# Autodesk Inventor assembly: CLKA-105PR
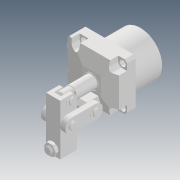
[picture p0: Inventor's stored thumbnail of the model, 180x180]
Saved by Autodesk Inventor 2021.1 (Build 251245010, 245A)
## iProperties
Created: 2018-07
Part Number: CLKA-105PR
Description: STEP AP203
Document SubType Name: Assembly
Designer: user
Title: CLKA-105P-R.STEP
Revision Number: ÈÎºÎ
Sending System: SolidWorks 2015
Preprocessor: SwSTEP 2.0
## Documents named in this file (11)
- D:\Vault_2016\Projekty\Clamptek\Hydraulic\CLKA-P\Inventor\CLKA-105PR\CLKA-105PR.iam
- D:\Vault_2016\Projekty\Clamptek\Hydraulic\CLKA-P\Inventor\CLKA-105PR\CLKA-105P-R-benti.ipt
- D:\Vault_2016\Projekty\Clamptek\Hydraulic\CLKA-P\Inventor\CLKA-105PR\duanxiao105.ipt
- D:\Vault_2016\Projekty\Clamptek\Hydraulic\CLKA-P\Inventor\CLKA-105PR\kahuang01.ipt
- D:\Vault_2016\Projekty\Clamptek\Hydraulic\CLKA-P\Inventor\CLKA-105PR\kahuang02.ipt
- D:\Vault_2016\Projekty\Clamptek\Hydraulic\CLKA-P\Inventor\CLKA-105PR\liangan105.ipt
- D:\Vault_2016\Projekty\Clamptek\Hydraulic\CLKA-P\Inventor\CLKA-105PR\luomu105.ipt
- D:\Vault_2016\Projekty\Clamptek\Hydraulic\CLKA-P\Inventor\CLKA-105PR\luosi105.ipt
- D:\Vault_2016\Projekty\Clamptek\Hydraulic\CLKA-P\Inventor\CLKA-105PR\yabi105.ipt
- D:\Vault_2016\Projekty\Clamptek\Hydraulic\CLKA-P\Inventor\CLKA-105PR\zhangxiao105.ipt
- D:\Vault_2016\Projekty\Clamptek\Hydraulic\CLKA-P\Inventor\CLKA-105PR\¶ÂÍ·G8-3.ipt
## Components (17 placed, 17 different names)
1. CLKA-105P-R-benti_1
2. duanxiao105_2
3. kahuang01_3
4. kahuang02_4
5. liangan105_5
6. luomu105_6
7. luosi105_7
8. yabi105_8
9. zhangxiao105_9
10. liangan105_10
11. zhangxiao105_11
12. kahuang01_12
13. kahuang01_13
14. kahuang01_14
15. kahuang02_15
16. ¶ÂÍ·G8-3_16
17. ¶ÂÍ·G8-3_17
